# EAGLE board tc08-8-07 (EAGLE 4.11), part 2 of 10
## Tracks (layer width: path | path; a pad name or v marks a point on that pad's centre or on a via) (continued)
BAC_04  (via drill 0.61) (continued)
  Top 0.254: v315.63,163.5 316.58,162.55 v316.58,161.28 | v338.81,163.5 339.44,162.86 339.44,158.1 v339.13,157.79 | v344.52,153.98 345.16,153.34 v345.16,147.62 | v363.89,147.31 361.67,145.08 361.67,134.93 362.3,134.29 362.3,129.53 364.84,126.99 v364.84,119.05 | v357.86,115.88 355.95,115.88 355.95,103.49 356.27,103.18 356.27,99.36 355.32,98.41 355.32,86.35 v354.05,85.08 | v328.01,80.63 v328.01,74.6 | v281.98,74.92 282.29,75.24 282.29,94.28 280.71,95.87 v280.71,96.19 | v277.53,103.18 277.53,107.3 C07.N2
  Route15 0.254: v309.28,168.58 v306.74,171.12
  Bottom 0.254: C07.N2 278.17,108.57 280.39,110.8 C07.M2 | v306.74,171.12 306.42,171.12 304.84,172.71 302.3,172.71 300.71,174.3 B06.M1 | v309.28,168.58 312.46,165.4 314.04,165.4 314.68,164.77 314.68,163.5 v315.63,163.5 | v316.58,161.28 318.49,163.18 338.49,163.18 v338.81,163.5 | v339.13,157.79 340.71,156.2 340.71,155.24 342.94,155.24 344.21,153.98 v344.52,153.98 | v345.16,147.62 357.86,147.62 358.18,147.31 v363.89,147.31 | v364.84,119.05 364.84,115.88 v357.86,115.88 | v354.05,85.08 353.73,84.76 346.75,84.76 346.43,85.08 336.9,85.08 336.27,84.44 331.82,84.44 v328.01,80.63 | v328.01,74.6 310.23,74.6 309.92,74.92 v281.98,74.92 | v280.71,96.19 280.39,96.51 272.13,96.51 271.5,97.14 267.69,97.14 267.05,97.78 267.05,99.36 267.37,99.36 268.01,100 269.28,100 269.59,100.32 274.04,100.32 276.9,103.18 v277.53,103.18
BAC_04\  (via drill 0.61)
  Top 0.254: v271.5,52.38 274.36,52.38 v274.36,49.2 | v318.49,63.49 318.17,63.81 318.17,65.71 317.54,66.35 317.54,68.57 318.81,69.84 v318.81,70.16 | v330.55,81.9 330.55,90.16 329.92,90.79 329.92,95.87 327.7,98.1 327.7,100.63 327.38,100.95 327.38,116.19 v328.97,117.78 | v297.22,173.02 297.22,177.15 B06.L1 | v302.3,162.86 301.98,162.55 301.98,158.1 303.57,156.52 v303.57,155.24 | v306.42,152.39 306.74,152.07 306.74,150.17 306.42,149.85 306.42,146.04 v307.69,144.77
  Route2 0.254: v246.1,47.29 v254.67,55.87 | v268.64,52.06 271.18,52.06 v271.5,52.38 | v315.63,59.36 315.63,60.63 v318.49,63.49 | v297.22,173.02 298.8,171.44 296.9,169.53 296.9,168.26 v302.3,162.86 | v306.42,152.39 v303.57,155.24
  Route15 0.254: v259.12,54.28 259.12,53.33 v261.66,50.79 | v287.69,49.83 288.33,49.83 v294.68,43.49 | v318.81,70.16 323.25,74.6 324.52,74.6 326.74,76.82 v326.11,77.46 | v335.32,117.78 336.27,116.83 336.27,112.7 337.54,111.43 C03.M1 | v307.69,144.77 310.87,141.59 310.87,140.96 321.66,130.16 321.66,129.53 326.74,124.45 326.74,120.96 327.06,120.64 327.06,119.69 v328.97,117.78
  Bottom 0.254: v246.1,47.29 243.56,47.29 D10.K2 | v254.67,55.87 255.31,55.23 258.16,55.23 v259.12,54.28 | v261.66,50.79 262.93,52.06 v268.64,52.06 | v274.36,49.2 274.67,48.88 284.52,48.88 285.47,49.83 v287.69,49.83 | v294.68,43.49 294.99,43.17 298.8,43.17 315,59.36 v315.63,59.36 | v326.11,77.46 v330.55,81.9 | v328.97,117.78 329.92,118.73 334.36,118.73 v335.32,117.78
BAC_05
  Bottom 0.254: B07.R1 284.83,165.4 287.06,167.63 B07.P1 288.01,168.58 288.96,169.53 294.36,169.53 295.63,168.26 B06.P1
BAC_05\  (via drill 0.61)
  Top 0.254: v297.85,160.33 297.85,161.59 295.63,163.82 295.63,169.85 296.58,170.8 B06.N1 | v296.26,143.18 v296.26,148.89
  Route15 0.254: v297.85,160.33 297.85,159.69 298.49,159.05 298.49,157.47 298.8,157.15 298.8,152.07 295.95,149.21 v296.26,148.89 | v303.88,141.59 304.52,141.59 306.74,139.37 306.74,138.42 336.27,108.89 336.27,106.99 337.86,105.4 C03.P1
  Bottom 0.254: v296.26,143.18 297.22,142.23 298.8,142.23 299.44,141.59 v303.88,141.59
BAC_06  (via drill 0.61)
  Top 0.254: v278.8,71.74 278.48,72.06 278.48,86.35 279.75,87.62 279.75,133.34 282.93,136.51 282.93,141.91 283.25,142.23 283.25,149.53 281.34,151.43 281.34,154.93 B07.U2 280.39,155.88 278.17,158.1 B07.T2
  Bottom 0.254: v278.8,71.74 271.5,71.74 270.23,70.47 268.32,70.47 266.42,68.57 238.8,68.57 237.21,66.98 D11.C1 | B06.S1 299.44,161.59 299.12,161.28 296.9,161.28 295.95,160.33 279.75,160.33 278.48,159.05 B07.T2
BAC_06\  (via drill 0.61)
  Top 0.254: v335.95,98.73 336.27,99.05 336.27,103.18 v334.36,105.08 | v297.85,162.86 297.22,163.5 297.22,164.45 B06.R1
  Route15 0.254: v334.36,105.08 322.62,116.83 322.62,117.14 321.98,117.78 321.03,117.78 299.76,139.05 299.76,141.27 298.8,142.23 298.8,151.12 302.61,154.93 302.61,156.52 v299.76,159.37
  Bottom 0.254: v335.95,98.73 337.54,98.73 C03.S1 | v299.76,159.37 301.34,160.96 301.34,163.18 298.17,163.18 v297.85,162.86
BAC_07  (via drill 0.61)
  Top 0.254: v228.32,86.66 228.64,86.35 228.64,66.35 229.59,65.39 229.59,61.27 229.91,60.95 D11.E2 | 288.64,133.02 288.64,134.93 | v288.64,86.66 288.64,133.02 | 288.64,134.93 287.69,135.88 C07.C1 | 288.64,133.02 v287.06,133.02 | v288.33,152.39 288.64,152.07 288.64,134.93
  Bottom 0.254: v228.32,86.66 v288.64,86.66 | v287.06,133.02 284.83,133.02 C07.D1 | v288.33,152.39 289.6,153.66 294.68,153.66 295.95,154.93 299.12,154.93 299.44,155.24 B06.U1
BAC_07\  (via drill 0.61)
  Top 0.254: v325.16,101.27 324.2,102.22 324.2,107.62 v324.84,108.25 | v308.33,124.77 306.74,126.35 306.74,128.26 306.11,128.89 305.15,128.89 305.15,134.61 v305.47,134.93 | v297.22,141.27 297.22,151.75 B06.V1
  Route15 0.254: v325.16,101.27 v334.36,92.06 | v324.84,108.25 322.93,110.16 322.93,110.8 316.9,116.83 316.27,116.83 v308.33,124.77 | v305.47,134.93 305.15,134.93 v300.71,139.37
  Bottom 0.254: v300.71,139.37 298.8,141.27 v297.22,141.27 | v334.36,92.06 C03.U1
BAC_08  (via drill 0.61)
  Top 0.254: v231.49,125.08 231.49,97.78 231.18,97.46 231.18,93.65 231.49,93.33 231.49,91.43 230.54,90.47 230.54,81.27 232.13,79.68 232.13,52.38 233.08,51.42 D11.J1 233.08,50.15 233.08,47.29 228.95,43.17 228.95,34.6 228.32,33.96 228.32,27.61 228.64,27.29 228.64,2.53 v228.95,2.21 | v290.23,198.74 290.23,197.47 B06.D2 | v288.33,202.55 288.64,202.87 288.64,204.14 289.91,205.41 289.91,220.97 289.28,221.6 289.28,234.3 288.96,234.62 288.96,258.11 288.33,258.75 288.33,262.56 288.64,262.88 288.64,287.96 288.96,288.28 v288.96,290.5 | v26.71,286.69 7.66,267.64 7.66,251.45 7.97,251.13 7.97,180.33 7.34,179.69 7.34,179.06 7.97,178.42 7.97,76.82 7.34,76.19 7.34,75.55 8.61,74.28 8.61,3.48 v8.29,3.16
  Route2 0.254: v290.23,198.74 290.23,200.33 288.33,202.24 v288.33,202.55
  Bottom 0.254: v231.49,125.08 273.09,125.08 274.67,126.67 277.21,126.67 C07.F2 278.48,127.3 280.71,129.53 C07.E2 | v288.96,290.5 288.64,290.82 271.18,290.82 270.55,290.18 237.53,290.18 236.89,289.55 218.79,289.55 218.48,289.86 216.57,289.86 215.94,290.5 214.67,290.5 213.4,289.23 212.13,289.23 211.49,288.6 208.95,288.6 208.32,287.96 190.54,287.96 189.9,288.6 184.82,288.6 183.55,287.32 142.28,287.32 141.96,287.64 134.34,287.64 132.75,286.05 86.71,286.05 86.08,286.69 85.44,286.69 84.17,285.42 60.68,285.42 60.04,286.05 51.47,286.05 50.84,286.69 v26.71,286.69 | v8.29,3.16 9.56,3.16 10.83,1.89 228.64,1.89 v228.95,2.21
BAC_08\  (via drill 0.61)
  Top 0.254: v327.7,142.55 327.38,142.23 327.38,132.7 327.7,132.39 327.7,128.26 328.33,127.62 C03.F2 | v319.12,166.04 319.44,166.36 319.44,166.68 320.39,167.63 320.39,171.44 317.54,174.3 v317.54,174.93 | v299.76,195.25 299.76,199.38 B06.C1
  Route15 0.254: v327.7,142.55 327.7,151.43 327.38,151.75 327.38,157.79 v319.12,166.04 | v317.54,174.93 317.54,179.37 310.23,186.68 309.92,186.68 302.61,193.98 v302.61,194.3
  Bottom 0.254: v302.61,194.3 301.66,195.25 v299.76,195.25
BAC_09  (via drill 0.61)
  Top 0.254: v291.18,192.71 291.18,191.44 290.87,191.12 B06.F2 | v307.69,194.93 308.01,194.61 v308.01,191.44 | v318.17,196.52 321.03,199.38 v321.03,201.28 | v356.91,204.46 358.81,204.46 358.81,205.73 v359.13,206.05 | v360.72,182.55 359.76,181.6 359.76,179.06 358.81,178.11 358.81,168.26 358.49,167.95 358.49,149.53 357.54,148.58 v357.54,144.77 | v286.42,126.35 286.1,126.03 286.1,119.05 287.06,118.1 C07.K1
  Route2 0.254: v318.17,196.52 v313.09,191.44 | v315.63,134.93 313.09,134.93 v309.92,131.75 | v290.23,130.16 v286.42,126.35
  Bottom 0.254: C07.J1 284.52,120 286.74,117.78 C07.K1 | v291.18,192.71 291.5,192.39 300.71,192.39 301.66,193.34 304.2,193.34 305.79,194.93 v307.69,194.93 | v308.01,191.44 308.33,191.76 312.77,191.76 v313.09,191.44 | v321.03,201.28 329.6,201.28 332.78,204.46 v356.91,204.46 | v359.13,206.05 360.4,204.77 362.3,204.77 364.21,202.87 366.75,202.87 367.38,202.24 367.38,182.55 v360.72,182.55 | v357.54,144.77 364.84,137.46 364.84,134.61 352.46,134.61 351.83,133.97 348.97,133.97 348.02,134.93 340.08,134.93 339.13,133.97 336.27,133.97 335.63,134.61 327.06,134.61 326.43,133.97 323.57,133.97 322.62,134.93 v315.63,134.93 | v309.92,131.75 309.6,132.07 292.45,132.07 290.55,130.16 v290.23,130.16
BAC_09\  (via drill 0.61)
  Top 0.254: v294.04,179.37 294.99,180.33 294.99,192.08 294.04,193.03 B06.E2 | v296.58,179.37 298.17,179.37 298.17,169.53 v297.85,169.21 | v328.01,124.13 328.33,123.81 328.33,121.27 C03.J2
  Route2 0.254: v296.58,179.37 v294.04,179.37 | v297.85,169.21 298.8,168.26 298.8,167.63 302.61,163.82 302.93,163.82 304.84,161.91 303.57,160.64 v303.57,160.33
  Route15 0.254: v303.57,160.33 311.19,152.71 311.19,150.8 312.46,149.53 312.46,146.67 319.44,139.69 319.44,138.1 326.74,130.8 326.74,125.4 v328.01,124.13
BAC_10\  (via drill 0.61)
  Top 0.254: v353.41,131.11 354.37,130.16 355.95,130.16 355.95,135.88 355.64,136.2 355.64,136.83 357.86,139.05 357.86,140.64 v360.72,143.5 | v364.21,157.15 363.57,157.79 v363.57,160.33 | v347.7,192.08 347.06,192.71 v347.06,193.98 | v348.97,210.81 348.97,212.39 349.6,213.03 349.6,222.24 348.97,222.87 v348.97,224.14 | v369.61,227 369.92,227.32 369.92,243.83 v368.02,245.73 | v366.11,247.32 366.43,247.64 v366.43,274.31 | v253.08,285.1 250.54,282.56 v250.54,267 | v294.04,189.85 294.04,187.95 B06.H2 | v328.01,212.71 v328.01,205.73
  Route2 0.254: v341.03,128.58 340.08,127.62 340.08,126.99 338.17,125.08 337.54,125.08 328.97,116.51 328.97,114.92 C03.L2 | v348.02,129.53 348.33,129.53 350.24,131.43 350.87,131.43 351.83,132.39 352.46,132.39 353.41,131.43 v353.41,131.11 | v344.52,198.11 342.3,200.33 343.57,201.6 343.57,203.51 346.11,206.05 346.11,207.95 v348.97,210.81 | v300.71,189.85 302.93,192.08 307.38,192.08 307.69,192.39 308.33,192.39 v318.17,202.24 | v328.01,205.73 v325.79,203.51
  Route15 0.254: v363.89,144.77 363.89,146.04 362.94,146.99 v362.94,151.12
  Bottom 0.254: v341.03,128.58 341.35,128.89 347.38,128.89 v348.02,129.53 | v360.72,143.5 361.99,144.77 v363.89,144.77 | v362.94,151.12 364.84,153.02 364.84,157.15 v364.21,157.15 | v363.57,160.33 363.26,160.64 362.94,160.64 361.67,161.91 361.67,163.82 355.95,163.82 355.64,164.14 355,164.14 354.68,163.82 347.06,163.82 346.43,164.45 346.43,166.36 348.33,166.36 348.97,166.99 357.86,166.99 358.49,167.63 358.49,170.49 357.86,170.49 348.97,179.37 348.97,192.08 v347.7,192.08 | v347.06,193.98 344.52,196.52 v344.52,198.11 | v348.97,224.14 348.97,226.68 352.46,226.68 353.1,226.05 355.95,226.05 356.91,227 v369.61,227 | v368.02,245.73 366.43,247.32 v366.11,247.32 | v366.43,274.31 366.43,283.83 355,283.83 353.73,285.1 v253.08,285.1 | v250.54,267 250.23,267.32 247.37,267.32 246.73,267.96 244.19,267.96 242.92,266.69 A10.D2 | v294.04,189.85 294.68,189.22 300.07,189.22 v300.71,189.85 | v318.17,202.24 321.35,202.24 321.66,201.92 324.2,201.92 v325.79,203.51 | v328.01,212.71 328.33,212.39 349.29,212.39 349.6,212.71 350.24,212.71 350.87,212.08 350.87,210.81 v348.97,210.81
BAC_11\  (via drill 0.61)
  Top 0.254: v232.45,96.83 231.81,96.19 231.81,93.97 232.13,93.65 232.13,88.25 232.45,87.94 v232.45,81.58 | v253.08,74.6 254.35,74.6 255.94,76.19 259.12,76.19 259.12,76.5 v259.43,76.82 | v267.69,75.87 272.77,75.87 273.72,76.82 v274.67,76.82 | v254.99,153.98 256.26,152.71 v256.26,144.77 | v254.67,126.67 253.72,125.72 253.72,118.73 v252.13,117.14
  Route2 0.254: 233.4,99.68 234.35,98.73 v232.45,96.83 | 233.4,99.68 230.86,102.22 230.22,102.22 229.91,101.91 227.68,101.91 C11.R2 | v247.05,80.63 v253.08,74.6 | v299.12,82.22 299.12,82.86 304.52,88.25 304.52,92.06 319.76,107.3 v320.08,107.3 | v258.48,174.3 255.31,171.12 255.31,169.85 254.35,168.9 254.35,166.04 v254.99,165.4 | v252.13,117.14 239.75,104.76 238.48,104.76 233.4,99.68
  Route15 0.254: v286.42,178.11 285.79,178.11 284.83,179.06 283.25,179.06 v282.61,178.42 | v244.51,161.59 244.51,158.42 v246.1,156.83 | v256.26,144.77 256.26,144.13 260.07,140.32 260.07,130.16 v261.66,128.58
  Bottom 0.254: v232.45,81.58 233.08,80.95 246.73,80.95 v247.05,80.63 | v259.43,76.82 259.75,77.14 266.42,77.14 v267.69,75.87 | v274.67,76.82 279.75,76.82 280.71,77.77 294.68,77.77 v299.12,82.22 | v320.08,107.3 320.71,106.67 327.06,106.67 328.01,107.62 C03.N2 | v286.42,178.11 286.74,178.11 287.69,179.06 291.5,179.06 293.09,180.64 B06.K2 | v282.61,178.42 281.98,179.06 275.31,179.06 272.13,175.88 260.07,175.88 v258.48,174.3 | v254.99,165.4 253.4,163.82 249.91,163.82 249.27,164.45 247.37,164.45 v244.51,161.59 | v246.1,156.83 250.86,156.83 253.72,153.98 v254.99,153.98 | v261.66,128.58 259.75,130.48 258.48,130.48 v254.67,126.67
BLK_IN_SYNC  (via drill 0.61)
  Top 0.254: v200.06,83.49 v200.06,95.87 | v146.4,85.39 146.4,100.63 145.77,101.27 v145.77,104.44 | v217.21,131.75 216.25,130.8 216.25,123.18 216.89,122.54 216.89,119.69 215.3,118.1 v215.3,116.51 | v221.97,116.19 221.97,113.65 v219.75,111.43 | v209.59,107.94 209.9,107.62 209.9,103.18 211.17,101.91 C13.S1
  Bottom 0.254: v200.06,95.87 200.7,96.51 204.82,96.51 206.73,98.41 C13.S1 | v200.06,83.49 199.74,83.81 194.03,83.81 192.76,85.08 185.77,85.08 185.14,84.44 182.28,84.44 181.01,85.71 146.72,85.71 v146.4,85.39 | v145.77,104.44 141.96,104.44 CD18.AP2 | v217.21,131.75 228.32,131.75 229.59,130.48 C11.E2 | v215.3,116.51 215.62,116.19 v221.97,116.19 | v219.75,111.43 218.16,109.84 212.76,109.84 210.86,107.94 v209.59,107.94
BLK_IN_SYNC\  (via drill 0.61)
  Top 0.254: v238.8,54.28 238.8,52.06 239.43,51.42 D10.J2 | v203.55,52.69 200.38,55.87 200.38,77.46 200.7,77.77 200.7,78.73 199.11,80.32 v199.11,89.21 | v247.69,270.18 248.64,271.13 248.64,275.26 248.96,275.58 A10.A1 | v203.24,260.66 v203.24,262.56 | v197.52,259.38 193.71,255.58 v193.71,253.67 | v183.23,243.83 183.87,243.19 183.87,239.38 182.92,238.43 182.92,236.52 183.87,235.57 183.87,232.71 v181.96,230.81 | v180.06,230.18 180.38,229.86 180.38,226.36 180.69,226.05 180.69,218.11 181.33,217.48 v181.33,213.03 | v172.76,203.51 171.8,202.55 171.8,198.74 v173.39,197.15 | v170.85,193.34 171.17,193.03 171.17,189.54 170.22,188.58 v170.22,188.27 | v178.79,159.69 178.15,159.05 178.15,154.61 178.47,154.29 178.47,153.34 177.52,152.39 177.52,151.12 175.93,149.53 175.93,143.5 v176.25,143.18
  Route2 0.254: v199.11,89.21 205.14,95.24 205.14,96.83 206.09,97.78 206.09,99.36 207.68,100.95 C13.R1 | v247.69,270.18 245.78,270.18 236.57,260.97 234.67,260.97 233.4,262.24 v230.54,259.38 | v193.71,253.67 193.08,253.67 v183.23,243.83 | v181.33,213.03 178.79,210.49 178.47,210.49 174.98,207 174.98,205.73 v172.76,203.51 | v173.39,197.15 173.39,195.89 v170.85,193.34 | v170.22,188.27 172.76,185.73 171.49,184.46 171.49,181.6 171.8,181.28 171.8,175.56 170.22,173.98 170.22,173.02 171.49,171.76 171.49,171.12 170.53,170.17 170.53,168.58 179.11,160.01 v178.79,159.69
  Route15 0.254: v218.48,261.29 217.21,261.29 v214.67,263.83 | v176.25,143.18 176.57,143.18 181.96,137.78 181.96,137.46 182.6,136.83 183.23,136.83 205.78,114.29 205.78,112.07 206.09,111.75 206.09,103.81 207.68,102.22 C13.R1
  Bottom 0.254: v238.8,54.28 237.21,52.69 v203.55,52.69 | v230.54,259.38 230.22,259.07 224.83,259.07 222.29,261.61 218.79,261.61 v218.48,261.29 | v214.67,263.83 213.08,262.24 209.9,262.24 209.59,262.56 205.78,262.56 205.46,262.24 203.55,262.24 v203.24,262.56 | v203.24,260.66 203.24,259.07 197.84,259.07 v197.52,259.38 | v181.96,230.81 181.33,230.18 v180.06,230.18
BMB_00
  Bottom 0.254: C08.B1 272.13,140.01 273.09,140.96 292.77,140.96 293.72,140.01 296.26,140.01 C06.B1
BMB_00\  (via drill 0.61)
  Top 0.254: v300.71,148.58 300.71,143.81 300.39,143.5 C06.A1 | v347.06,149.21 346.75,148.89 346.75,140.96 347.38,140.32 C02.B1
  Bottom 0.254: v300.71,148.58 301.03,148.26 313.09,148.26 313.73,148.89 320.39,148.89 320.71,149.21 v347.06,149.21
BMB_01
  Bottom 0.254: C08.H1 275.31,124.13 276.26,125.08 279.12,125.08 282.61,128.58 295.95,128.58 297.22,129.84 299.44,129.84 C06.E1
BMB_01\  (via drill 0.61)
  Top 0.254: v297.22,136.83 297.22,133.97 C06.D1 | v305.47,138.74 306.42,139.69 306.42,140.96 308.65,143.18 308.65,150.17 v308.33,150.48 | v355.32,151.12 355.32,137.46 355,137.15 355,134.29 355.32,133.97 355.32,131.75 v354.68,131.11
  Bottom 0.254: v297.22,136.83 298.17,137.78 304.52,137.78 v305.47,138.74 | v308.33,150.48 308.65,150.17 319.76,150.17 320.39,150.8 355,150.8 v355.32,151.12 | v354.68,131.11 353.73,130.16 C02.E1
BMB_02
  Bottom 0.254: C08.N1 272.13,108.25 273.09,109.21 276.26,109.21 283.25,116.19 288.96,116.19 296.26,123.49 299.44,123.49 C06.H1
BMB_02\  (via drill 0.61)
  Top 0.254: v305.47,127.94 305.15,127.62 305.15,109.21 307.69,106.67 v307.69,103.49 | v355.32,102.86 v355.32,123.49
  Bottom 0.254: v305.47,127.94 305.15,128.26 298.49,128.26 297.53,127.3 C06.F1 | v307.69,103.49 310.55,103.49 311.19,102.86 v355.32,102.86 | v355.32,123.49 351.51,123.49 C02.H1
BMB_03  (via drill 0.61)
  Top 0.254: v269.91,123.81 269.91,124.13 268.96,125.08 268.96,129.21 268.64,129.53 C08.E2 | v293.41,121.91 v293.41,119.05
  Bottom 0.254: v269.91,123.81 270.55,123.18 273.4,123.18 274.04,122.54 279.44,122.54 280.07,121.91 v293.41,121.91 | v293.41,119.05 293.72,118.73 297.22,118.73 298.17,117.78 299.44,117.78 C06.K1
BMB_03\  (via drill 0.61)
  Top 0.254: v307.38,119.69 308.01,119.05 308.01,107.94 308.33,107.62 308.33,104.76 311.19,101.91 v311.19,100.95 | v339.13,100.95 339.44,101.27 339.44,112.38 v339.13,112.7 | v350.56,112.7 350.56,116.83 C02.K1
  Bottom 0.254: v307.38,119.69 307.06,119.37 298.49,119.37 297.53,120.32 C06.J1 | v311.19,100.95 311.82,100.32 338.49,100.32 v339.13,100.95 | v339.13,112.7 v350.56,112.7
BMB_04  (via drill 0.61)
  Top 0.254: v265.15,109.52 C08.L2
  Bottom 0.254: v265.15,109.52 265.47,109.21 268.32,109.21 270.86,106.67 280.71,106.67 283.25,109.21 294.04,109.21 295.95,111.11 C06.M1
BMB_04\  (via drill 0.61)
  Top 0.254: v300.39,106.67 v300.39,109.52 | v306.11,102.86 308.01,100.95 v308.01,97.78 | v320.71,97.14 320.39,97.46 320.39,103.81 v320.71,104.13 | v350.56,106.35 350.56,110.48 C02.M1
  Bottom 0.254: v300.39,109.52 301.03,110.16 301.34,110.16 301.34,111.75 300.71,112.38 299.12,112.38 297.53,113.97 C06.L1 | v300.39,106.67 301.98,105.08 303.88,105.08 v306.11,102.86 | v308.01,97.78 308.33,97.46 311.82,97.46 312.14,97.14 v320.71,97.14 | v320.71,104.13 321.35,103.49 346.43,103.49 349.29,106.35 v350.56,106.35
BMB_05
  Bottom 0.254: C08.S2 268.96,98.73 269.91,99.68 292.14,99.68 292.77,100.32 297.53,100.32 299.76,102.54 299.76,104.13 C06.P1
BMB_05\  (via drill 0.61)
  Top 0.254: v284.52,106.03 282.93,104.44 282.93,99.68 v283.88,98.73 | v308.96,99.68 310.87,97.78 v310.87,96.51 | v350.24,100.32 350.56,100.63 350.56,104.13 C02.P1
  Bottom 0.254: v284.52,106.03 291.82,106.03 292.45,106.67 295.31,106.67 296.26,107.62 C06.N1 | v283.88,98.73 285.47,97.14 288.96,97.14 290.87,99.05 292.45,99.05 293.09,99.68 v308.96,99.68 | v310.87,96.51 320.08,96.51 320.39,96.19 321.35,96.19 321.98,96.83 329.92,96.83 330.24,96.51 334.36,96.51 334.68,96.83 336.9,96.83 337.22,96.51 346.43,96.51 v350.24,100.32
BMB_06  (via drill 0.61)
  Top 0.254: v295.95,98.41 295.63,98.73 295.63,104.76 v295.95,105.08 | v293.41,126.99 292.77,127.62 292.77,129.21 292.45,129.53 292.45,133.34 v293.72,134.61 | v294.68,138.1 294.36,138.42 v294.36,140.96 | v290.55,143.5 290.23,143.81 v290.23,148.89
  Route2 0.254: v293.72,134.61 295.31,136.2 295.31,137.46 v294.68,138.1
  Route15 0.254: v295.95,105.08 295.95,106.99 295.63,107.3 295.63,109.52 295.31,109.84 295.31,117.14 298.8,120.64 298.49,120.96 298.49,121.91 v293.41,126.99 | v293.41,148.89 295.95,151.43 295.63,151.75 295.63,158.1 295.31,158.42 295.31,162.86 284.2,173.98 284.2,175.56 279.75,180.01 279.75,185.09 274.04,190.8 274.04,192.39 273.4,193.03 273.4,200.96 271.82,202.55 B08.B1
  Bottom 0.254: v294.36,140.96 294.04,141.27 293.41,141.27 291.18,143.5 v290.55,143.5 | v290.23,148.89 v293.41,148.89 | v295.95,98.41 C06.S1
BMB_06\  (via drill 0.61)
  Top 0.254: v275.63,100.63 275.94,100.32 275.94,88.89 274.99,87.94 v274.99,84.76 | v351.19,93.65 351.19,97.78 C02.S1
  Bottom 0.254: v275.63,100.63 275.94,100.32 291.18,100.32 291.82,100.95 295.95,100.95 296.26,101.27 C06.R1 | v274.99,84.76 282.29,84.76 283.56,86.03 288.01,86.03 288.33,85.71 335.63,85.71 336.27,86.35 350.24,86.35 350.56,86.03 351.19,86.03 352.14,86.98 352.14,93.65 v351.19,93.65
BMB_07  (via drill 0.61)
  Top 0.254: v299.76,95.55 299.76,92.7 C06.U1 | v269.91,130.16 270.23,130.48 270.23,141.91 270.55,142.23 270.55,151.43 269.59,152.39 269.59,156.83 269.28,157.15 269.28,160.96 269.59,161.28 v269.59,172.39 | v274.99,191.12 274.99,193.03 B08.E1
  Route2 0.254: v269.59,172.39 269.59,172.71 270.86,173.98 270.86,176.2 268.64,178.42 270.23,180.01 270.23,186.36 v274.99,191.12
  Route15 0.254: v299.76,95.55 299.76,95.87 291.82,103.81 291.82,108.57 290.23,110.16 290.23,111.11 289.28,112.07 289.28,113.33 278.17,124.45 277.53,124.45 273.4,128.58 273.4,128.89 272.77,129.53 270.55,129.53 v269.91,130.16
BMB_07\
  Bottom 0.254: C06.V1 297.53,88.57 299.76,86.35 330.55,86.35 334.36,90.16 348.65,90.16 350.24,91.74 C02.U1
BMB_08  (via drill 0.61)
  Top 0.254: v290.23,136.2 290.23,133.97 C06.D2 | v280.71,139.37 282.29,140.96 282.29,142.23 282.61,142.55 282.61,147.62 279.44,150.8 279.44,155.56 v279.12,155.88 | v279.44,164.77 280.39,163.82 281.66,163.82 281.66,166.99 282.93,168.26 282.93,173.66 283.56,174.3 283.56,176.2 279.75,180.01 279.75,184.77 v280.71,185.73
  Route15 0.254: v279.12,155.88 279.12,164.45 v279.44,164.77
  Bottom 0.254: v290.23,136.2 288.01,138.42 288.01,139.37 285.79,139.37 284.83,138.42 283.56,138.42 282.93,139.05 282.93,140.32 281.66,140.32 v280.71,139.37 | v280.71,185.73 279.12,187.31 279.12,188.9 275.94,188.9 271.5,193.34 268.96,193.34 B08.E2
BMB_08\  (via drill 0.61)
  Top 0.254: v339.44,140.96 339.44,127.62 v339.13,127.3
  Bottom 0.254: v339.44,140.96 334.36,140.96 334.05,140.64 330.24,140.64 329.92,140.96 321.66,140.96 320.71,140.01 318.17,140.01 316.58,138.42 306.42,138.42 305.15,137.15 301.03,137.15 300.71,136.83 C06.C1 | v339.13,127.3 340.71,127.3 C02.F2
BMB_09  (via drill 0.61)
  Top 0.254: v307.69,126.67 307.69,135.88 308.33,136.51 308.33,140.32 309.28,141.27 v309.92,141.27 | v311.82,141.27 311.5,141.59 v311.5,149.21 | v370.56,166.99 v370.56,157.47 | v323.89,209.22 323.57,208.9 323.57,193.66 v323.25,193.34 | v279.44,189.85 279.12,189.54 v279.12,174.93
  Bottom 0.254: v307.69,126.67 307.38,126.35 304.84,126.35 304.2,125.72 292.14,125.72 291.18,126.67 C06.F2 | v311.82,141.27 v309.92,141.27 | v311.5,149.21 311.82,149.53 320.08,149.53 320.71,150.17 363.26,150.17 v370.56,157.47 | v370.56,166.99 370.56,209.22 v323.89,209.22 | v323.25,193.34 322.3,192.39 301.66,192.39 301.03,191.76 282.93,191.76 281.02,189.85 v279.44,189.85 | v279.12,174.93 275.31,174.93 B08.M1
BMB_09\  (via drill 0.61)
  Top 0.254: v320.71,129.53 321.03,129.21 321.03,120 v321.98,119.05
  Bottom 0.254: v320.71,129.53 320.08,128.89 305.79,128.89 303.25,131.43 295.31,131.43 294.36,130.48 C06.E2 | v321.98,119.05 322.3,119.37 337.22,119.37 337.54,119.69 340.08,119.69 340.71,120.32 C02.J2
BMB_10  (via drill 0.61)
  Top 0.254: v290.23,125.08 290.23,121.27 C06.J2 | v280.71,127.94 v280.71,125.4 | v274.99,128.26 v274.99,125.72 | v272.45,128.58 272.77,128.89 272.77,142.55 272.13,143.18 272.13,151.12 272.77,151.75 272.77,156.52 v272.45,156.83 | v274.36,157.15 v274.36,159.69 | v272.45,160.96 271.82,161.59 271.82,164.45 B08.R1
  Bottom 0.254: v290.23,125.08 289.91,125.4 v280.71,125.4 | v280.71,127.94 278.48,125.72 v274.99,125.72 | v274.99,128.26 274.67,128.58 v272.45,128.58 | v272.45,156.83 272.77,157.15 v274.36,157.15 | v274.36,159.69 273.09,160.96 v272.45,160.96
BMB_10\  (via drill 0.61)
  Top 0.254: v294.36,120 294.36,122.86 294.04,123.18 C06.H2 | v334.36,109.52 335,110.16 v335,112.07
  Bottom 0.254: v294.36,120 294.99,119.37 297.53,119.37 298.17,118.73 308.33,118.73 308.65,119.05 313.09,119.05 314.04,118.1 314.04,115.56 308.65,115.56 305.15,112.07 305.15,109.84 323.25,109.84 323.89,109.21 334.05,109.21 v334.36,109.52 | v335,112.07 336.9,113.97 340.71,113.97 C02.L2
BMB_11  (via drill 0.61)
  Top 0.254: v290.23,118.73 290.23,114.92 C06.L2 | v276.9,130.48 276.58,130.8 276.58,136.2 v276.26,136.51 | v269.28,139.37 269.59,139.69 269.59,142.23 269.91,142.55 269.91,149.85 v269.28,150.48 | v266.1,162.86 266.42,163.18 266.42,166.04 264.83,167.63 v264.83,168.26 | v274.99,176.2 274.36,176.83 v274.36,179.37
  Route2 0.254: v271.18,137.46 v269.28,139.37 | v259.75,156.52 v266.1,162.86 | v274.36,172.39 275.94,173.98 275.94,175.25 v274.99,176.2
  Route15 0.254: v287.37,120 v276.9,130.48 | v274.36,179.37 273.4,180.33 273.4,181.92 271.82,183.5 B08.J1
  Bottom 0.254: v290.23,118.73 288.96,120 v287.37,120 | v276.26,136.51 276.26,137.78 271.5,137.78 v271.18,137.46 | v269.28,150.48 262.93,150.48 260.07,153.34 260.07,156.52 v259.75,156.52 | v264.83,168.26 264.83,170.17 266.42,170.17 266.74,170.49 270.55,170.49 270.86,170.17 272.13,170.17 v274.36,172.39
BMB_11\  (via drill 0.61)
  Top 0.254: v308.96,118.1 311.19,115.88 v311.19,108.25
  Bottom 0.254: v308.96,118.1 307.06,116.19 295.31,116.19 294.36,117.14 C06.K2 | v311.19,108.25 313.41,106.03 336.27,106.03 338.17,107.94 C02.N2
BMB_TO_DTB  (via drill 0.61)
  Top 0.254: 271.18,124.77 271.18,126.35 C08.F1 | 271.18,124.77 271.18,123.81 269.28,121.91 269.28,118.73 268.64,118.1 C08.K2 | 273.4,122.54 273.4,116.83 274.36,115.88 274.36,111.75 C08.M1 | 271.18,124.77 273.4,122.54 | 273.4,122.54 273.4,141.27 274.36,142.23 C08.A1 274.36,143.5 274.36,153.98 273.4,154.93 273.4,171.44 | B08.A1 274.04,206.05 274.04,201.28 273.4,200.65 273.4,188.9 274.36,187.95 B08.H1 274.36,186.68 273.4,185.73 273.4,173.98 273.72,173.66 273.72,173.02 272.77,172.07 | 273.4,171.44 274.36,170.49 274.36,168.9 B08.P1 | 273.4,171.44 272.77,172.07 | 272.77,172.07 271.82,173.02 271.82,177.15 B08.L1 271.18,178.42 270.23,179.37 270.23,195.25 271.18,196.2 B08.D1 | v221.97,75.87 221.97,46.03 221.02,45.07 D12.L1 | v263.24,76.19 263.24,96.83 264.83,98.41 264.83,100.95 C08.R2 264.83,102.22 263.88,103.18 263.88,127.62 265.15,128.89 265.15,130.48 | 265.15,130.48 C08.D2 | 265.15,130.48 v265.47,130.48
  Bottom 0.254: B08.D1 B08.D2 | v221.97,75.87 262.93,75.87 v263.24,76.19 | v265.47,130.48 267.05,128.89 269.28,128.89 270.86,127.3 C08.F1
BMR00  (via drill 0.61)
  Top 0.254: v85.44,260.02 86.08,259.38 86.08,240.65 87.67,239.06 v87.67,238.43 | v96.56,236.21 97.19,235.57 v97.19,234.3 | v121.32,233.35 121,233.03 121,229.22 121.64,228.59 121.64,226.68 120.69,225.73 v120.69,221.92 | v150.21,210.81 151.17,209.86 v151.17,207
  Route15 0.254: v120.69,221.92 120.69,220.02 v122.59,218.11 | v151.17,207 151.48,207 156.56,201.92 160.37,201.92 190.22,172.07 190.22,170.49 191.81,168.9 B14.P2
  Bottom 0.254: v85.44,260.02 81.63,260.02 A23.F1 | v87.67,238.43 89.25,236.84 95.92,236.84 v96.56,236.21 | v97.19,234.3 98.14,233.35 v121.32,233.35 | v122.59,218.11 124.81,215.89 145.45,215.89 150.21,211.12 v150.21,210.81
BMR00\  (via drill 0.61)
  Top 0.254: v84.49,254.94 84.49,256.53 A23.H1 | v128.31,255.58 129.26,254.62 129.26,252.08 130.21,251.13 130.21,241.61 127.35,238.75 127.35,232.4 127.04,232.08 127.04,229.54 v127.35,229.22 | v131.48,225.09 130.53,224.14 130.53,211.44 130.85,211.12 130.85,204.14 130.53,203.82 130.53,196.2 130.85,195.89 130.85,191.44 130.53,191.12 130.53,189.85 132.12,188.27 v132.12,187.63
  Route2 0.254: v131.48,225.09 v127.35,229.22
  Route15 0.254: v161.96,186.68 162.91,186.68 168.63,180.96 170.53,180.96 v186.09,165.4
  Bottom 0.254: v84.49,254.94 84.81,255.26 124.81,255.26 125.13,255.58 v128.31,255.58 | v132.12,187.63 133.7,186.04 161.01,186.04 161.64,186.68 v161.96,186.68 | v186.09,165.4 188.31,165.4 B14.R2
BMR01  (via drill 0.61)
  Top 0.254: v82.59,268.59 82.59,271.13 81.32,272.4 A23.B1 | v104.49,266.37 105.13,265.74 105.13,246.37 v106.72,244.78 | v152.12,242.56 152.75,241.92 v152.75,228.9 | v160.37,222.24 160.69,221.92 v160.69,213.03 | v164.82,212.39 v169.58,207.63
  Route2 0.254: v157.52,225.09 v160.37,222.24
  Route15 0.254: v169.58,207.63 176.25,207.63 180.38,203.51 180.69,203.51 181.33,202.87 181.33,202.24 191.49,192.08 191.49,191.76 192.12,191.12 194.35,191.12 194.66,190.8 B14.F1
  Bottom 0.254: v82.59,268.59 83.22,267.96 95.29,267.96 95.92,267.32 98.78,267.32 99.41,267.96 101.32,267.96 102.91,266.37 v104.49,266.37 | v106.72,244.78 108.94,242.56 v152.12,242.56 | v152.75,228.9 156.56,225.09 v157.52,225.09 | v160.69,213.03 161.33,212.39 v164.82,212.39
BMR01\  (via drill 0.61)
  Top 0.254: v91.48,254.3 88.62,257.16 88.62,263.51 86.08,266.05 86.08,269.86 85.13,270.81 85.13,274.94 84.49,275.58 A23.A1 | v134.66,252.4 v136.56,254.3 | v162.28,257.16 v165.14,260.02 | v169.58,262.88 171.8,260.66 171.8,254.3 172.44,253.67 172.44,252.08 171.8,251.45 171.8,242.24 v173.39,240.65 | v185.46,229.86 185.46,227 184.5,226.05 v184.5,222.55 | v187.04,222.55 186.09,221.6 v186.09,216.21 | v188.63,215.57 189.58,214.62 v189.58,207.63
  Route15 0.254: v173.39,240.65 v181.96,232.08 | v189.58,207.63 189.58,204.46 196.57,197.47 196.57,195.89 198.16,194.3 B14.E1
  Bottom 0.254: v91.48,254.3 96.24,249.54 110.84,249.54 113.38,252.08 124.5,252.08 124.81,251.77 127.67,251.77 128.31,252.4 v134.66,252.4 | v136.56,254.3 137.51,255.26 160.37,255.26 v162.28,257.16 | v165.14,260.02 167.99,262.88 v169.58,262.88 | v181.96,232.08 184.19,229.86 v185.46,229.86 | v184.5,222.55 v187.04,222.55 | v186.09,216.21 186.73,215.57 v188.63,215.57
C00  (via drill 0.61)
  Top 0.254: v181.33,148.58 181.33,136.51 180.69,135.88 180.69,131.75 179.74,130.8 C15.E2 | v41.63,274.31 41.63,265.74 40.04,264.15 A26.E2 | v212.76,280.66 212.44,280.34 212.44,250.18 214.03,248.59 214.03,248.27 A12.L2 214.03,247 213.08,246.05 213.08,220.33 214.35,219.06 214.35,205.09 213.08,203.82 213.08,168.26 214.03,167.31 214.03,165.72 B12.R2 214.03,164.45 211.81,162.23 B13.S1 211.49,161.28 212.44,160.33 212.44,149.53 v211.81,148.89 212.76,147.94 212.76,146.99 212.44,146.67 v212.44,86.03 | v250.23,84.76 250.23,79.68 250.54,79.36 250.54,68.25 249.59,67.3 D10.C1
  Bottom 0.254: v181.33,148.58 181.65,148.26 188.63,148.26 188.95,148.58 205.14,148.58 205.46,148.89 v211.81,148.89 | v41.63,274.31 42.26,274.94 53.06,274.94 57.19,279.07 136.24,279.07 137.83,280.66 138.47,280.66 138.78,280.34 212.44,280.34 v212.76,280.66 | v250.23,84.76 241.65,84.76 241.02,85.39 229.27,85.39 228.95,85.08 226.1,85.08 224.83,86.35 212.76,86.35 v212.44,86.03
C00\  (via drill 0.61)
  Top 0.254: v180.06,148.58 177.52,146.04 177.52,122.22 176.57,121.27 C15.J2 | v187.04,164.45 187.04,185.73 186.09,186.68 B15.H1 186.09,187.95 186.09,192.08 187.68,193.66 187.68,217.16 v188.63,218.11 | v195.62,237.16 193.39,234.94 193.39,223.83 192.76,223.19 v192.76,218.11 | B13.U1 210.86,156.2 210.22,156.83 210.22,160.96 209.9,161.28 209.9,166.68 210.86,167.63 B13.P1
  Bottom 0.254: v180.06,148.58 181.01,149.53 184.82,149.53 185.46,148.89 188.31,148.89 188.63,149.21 204.82,149.21 206.09,150.48 208.95,150.48 210.86,152.39 210.86,154.93 B13.U1 | B13.P1 210.86,167.63 210.86,166.04 208.63,163.82 207.05,163.82 205.46,162.23 B13.S2 201.01,161.91 199.74,163.18 188.31,163.18 v187.04,164.45 | v195.62,237.16 195.93,236.84 215.94,236.84 216.89,237.8 A12.P2 | v188.63,218.11 v192.76,218.11
C01  (via drill 0.61)
  Top 0.254: 228.32,170.8 228.32,180.01 228.95,180.64 228.95,181.6 v229.91,182.55 | 228.32,170.8 228.32,158.1 227.37,157.15 227.37,153.02 B11.V2 | v206.41,170.49 206.41,170.17 205.14,168.9 B13.P2 | 228.32,170.8 v228.64,170.8 | v37.82,278.43 37.82,268.91 38.14,268.59 38.14,266.37 37.82,266.05 37.82,261.93 36.87,260.97 A26.F2 | v213.71,285.74 213.71,274.31 213.08,273.67 213.08,252.72 218.16,247.64 218.16,244.78 A12.M2 217.52,240.97 218.79,239.7 218.79,227.95 221.33,225.41 221.33,223.51 v222.29,222.55 | v247.69,193.03 244.83,195.89 244.83,220.65 244.19,221.29 v244.19,223.51
  Bottom 0.254: v229.91,182.55 230.22,182.87 244.51,182.87 245.46,183.82 B10.J1 246.42,184.77 246.42,189.22 246.73,189.22 247.69,190.17 v247.69,193.03 | v206.41,170.49 206.73,170.17 228,170.17 v228.64,170.8 | v37.82,278.43 43.53,284.15 57.5,284.15 58.77,282.88 134.34,282.88 135.93,284.47 140.37,284.47 140.69,284.15 185.14,284.15 186.41,285.42 188.31,285.42 188.95,284.79 209.9,284.79 210.54,285.42 213.4,285.42 v213.71,285.74 | v244.19,223.51 226.1,223.51 225.14,222.55 v222.29,222.55
C01\  (via drill 0.61)
  Top 0.254: B13.R2 202.28,165.4 202.92,166.04 202.92,169.53 204.82,171.44 B13.M2 204.51,175.25 203.55,176.2 203.55,182.87 v204.19,183.5 | v216.57,234.62 216.25,234.3 216.25,219.06 214.98,217.79 214.98,204.46 215.94,203.51 215.94,199.38 216.25,199.06 216.25,198.43 | 216.25,198.43 216.25,186.36 v216.89,185.73 | D10.D1 245.78,64.12 245.46,64.44 245.46,68.57 244.83,69.2 244.83,94.6 244.51,94.92 244.51,96.19 244.83,96.51 244.83,125.72 v244.51,126.03 v244.51,129.21 | v248.96,163.5 248.96,167.63 B10.P1 248.96,168.9 v248.96,171.76 | v248.96,160.33 248.64,160.01 248.64,156.83 248,156.2 248,146.04 251.18,142.86 251.18,130.8 v251.5,130.48 | v216.57,198.43 216.25,198.43 | v242.29,190.17 241.65,189.54 241.65,177.47 v242.61,176.52
  Bottom 0.254: v216.57,234.62 214.98,234.62 A12.R2 | v216.89,185.73 216.57,185.41 211.17,185.41 208.63,182.87 204.82,182.87 v204.19,183.5 | v244.51,126.03 244.19,125.72 232.13,125.72 231.81,126.03 228,126.03 227.68,125.72 215.94,125.72 214.98,126.67 C12.F2 | v248.96,163.5 248,162.55 248,160.96 248.32,160.96 v248.96,160.33 | v251.5,130.48 249.91,128.89 244.83,128.89 v244.51,129.21 | v216.57,198.43 221.97,198.43 222.92,197.47 225.78,197.47 226.73,198.43 234.67,198.43 238.16,194.93 243.56,194.93 244.83,193.66 244.83,190.17 v242.29,190.17 | v242.61,176.52 243.24,175.88 243.56,175.88 245.46,173.98 246.73,173.98 v248.96,171.76
CK00  (via drill 0.61)
  Top 0.254: v174.03,159.69 174.34,160.01 174.34,177.15 171.8,179.69 171.8,183.18 v172.44,183.82 | v156.56,187.63 155.93,188.27 155.93,194.3 156.25,194.61 156.25,195.89 155.93,196.2 155.93,205.09 v156.25,205.41 | v144.82,207 144.18,207.63 v144.18,210.17 | v129.89,210.81 129.89,224.78 130.53,225.41 v130.53,237.16
  Route2 0.254: v174.03,159.69 v175.93,161.59
  Route15 0.254: v192.76,159.69 v194.66,161.59 | v182.92,162.55 v185.77,159.69 | v172.44,183.82 172.12,183.82 v167.04,188.9
  Bottom 0.254: v194.66,161.59 197.84,161.59 B14.S1 | v192.76,159.69 192.44,160.01 186.09,160.01 v185.77,159.69 | v182.92,162.55 182.28,163.18 178.47,163.18 176.88,161.59 v175.93,161.59 | v167.04,188.9 166.72,188.58 159.42,188.58 158.47,187.63 v156.56,187.63 | v156.25,205.41 155.93,205.09 147.04,205.09 145.13,207 v144.82,207 | v144.18,210.17 143.55,210.81 v129.89,210.81 | v130.53,237.16 130.85,236.84 138.78,236.84 139.74,237.8 140.69,237.8 A18.P2
CK00\  (via drill 0.61)
  Top 0.254: v188.95,154.29 B14.T2 188.95,162.55 187.68,162.55 186.41,163.82 v185.46,163.82 | v140.37,240.97 142.59,238.75 v142.59,228.9 | v126.72,225.41 127.99,224.14 v127.99,213.98 | v146.72,212.71 146.4,212.39 v146.4,195.57 | v163.23,194.93 164.82,193.34 v164.82,186.36 | v169.58,180.01 168.63,179.06 168.63,174.61 171.49,171.76 v171.49,169.85
  Route2 0.254: v164.82,186.36 164.82,184.77 v169.58,180.01
  Route15 0.254: v154.98,196.2 155.61,196.2 v157.2,194.61 | v176.57,167.95 179.42,165.09 180.06,165.09 v181.01,164.14
  Bottom 0.254: v188.95,154.29 193.08,154.29 193.71,154.93 195.93,154.93 196.25,155.24 197.84,155.24 B14.U1 | v140.37,240.97 138.78,240.97 A18.N2 | v142.59,228.9 141.32,227.64 139.1,227.64 138.47,227 128.31,227 v126.72,225.41 | v127.99,213.98 145.45,213.98 v146.72,212.71 | v146.4,195.57 154.34,195.57 v154.98,196.2 | v157.2,194.61 157.52,194.93 v163.23,194.93 | v171.49,169.85 171.8,169.53 174.98,169.53 v176.57,167.95 | v181.01,164.14 181.33,163.82 v185.46,163.82
CK01  (via drill 0.61)
  Top 0.254: C16.N1 169.58,107.3 169.58,102.22 C16.R1 | v196.57,154.29 197.2,154.93 197.2,164.14 198.16,165.09 198.16,167.63 B14.P1 | v157.52,109.52 155.29,111.75 155.29,135.88 155.61,136.2 v155.61,137.46 | v158.47,137.78 158.47,164.77 v158.79,165.09
  Bottom 0.254: C16.R1 170.53,101.91 172.76,104.13 C16.P1 | v196.57,154.29 194.03,154.29 193.39,153.66 190.54,153.66 189.58,152.71 B14.V2 | v157.52,109.52 157.83,109.21 164.18,109.21 164.82,108.57 168.95,108.57 169.26,108.25 C16.N1 | v155.61,137.46 155.93,137.78 v158.47,137.78 | v158.79,165.09 160.06,166.36 178.79,166.36 179.42,166.99 180.69,166.99 181.01,167.31 184.82,167.31 185.14,166.99 193.39,166.99 194.66,168.26 B14.P1
CK01\  (via drill 0.61)
  Top 0.254: C16.U2 166.09,92.38 163.87,94.6 C16.T2 164.18,95.55 166.41,97.78 C16.S2 | v194.66,143.18 194.66,151.43 194.98,151.75 B14.V1 | v138.78,137.46 137.83,136.51 v137.83,135.88 | v127.04,135.56 126.72,135.24 v126.72,100.32
  Route2 0.254: v194.66,143.18 193.71,142.23 193.71,140.96 189.9,137.15 187.68,137.15 v186.73,138.1
  Bottom 0.254: v186.73,138.1 186.41,137.78 184.19,137.78 183.23,136.83 181.01,136.83 179.42,138.42 159.1,138.42 158.79,138.74 158.15,138.74 157.83,138.42 139.74,138.42 v138.78,137.46 | v137.83,135.88 137.2,135.24 127.35,135.24 v127.04,135.56 | v126.72,100.32 127.35,99.68 161.33,99.68 161.64,100 164.5,100 165.77,98.73 166.09,98.73 C16.S2
CLR_DF\  (via drill 0.61)
  Top 0.254: v235.62,55.55 235.3,55.87 235.3,60.95 235.94,61.58 v235.94,62.22 | v216.89,108.25 216.25,108.89 216.25,112.07 217.21,113.02 v217.21,115.24 | v220.06,123.18 219.43,123.81 219.43,135.56 220.38,136.51 v220.38,137.46 | v236.89,184.77 235.3,186.36 235.3,195.89 236.89,197.47 v238.16,197.47 | v240.38,212.71 v240.38,217.16 | v236.89,217.16 236.89,224.78 A11.U1
  Route2 0.254: v235.62,55.55 228.32,48.25 228.32,43.8 227.05,42.53 D11.N2 | v217.21,115.24 218.79,116.83 218.79,121.91 v220.06,123.18 | v220.38,137.46 230.54,147.62 230.54,149.21 232.13,150.8 232.13,153.02 v242.61,163.5 | v238.16,197.47 238.16,199.38 241.02,202.24 241.02,212.08 v240.38,212.71
  Route15 0.254: v235.94,62.22 240.07,66.35 235.62,70.79 235.62,72.06 235.3,72.38 235.3,73.97 v231.18,78.09 | v235.94,79.36 238.48,81.9 232.13,88.25 232.13,92.06 217.84,106.35 217.52,106.35 216.89,106.99 v216.89,108.25 | v244.19,165.09 238.48,170.8 238.48,175.88 235.3,179.06 235.3,183.18 v236.89,184.77
  Bottom 0.254: v231.18,78.09 232.45,79.36 v235.94,79.36 | v242.61,163.5 v244.19,165.09 | v240.38,217.16 v236.89,217.16
CLR_DTF\  (via drill 0.61)
  Top 0.254: v211.49,80.32 211.49,91.43 C13.U1 | v208.32,77.14 207.36,76.19 207.36,71.11 206.41,70.16 206.41,52.06 206.09,51.74 206.09,24.75 v206.73,24.12
  Bottom 0.254: v208.32,77.14 v211.49,80.32 | v206.73,24.12 207.05,23.8 212.44,23.8 213.4,22.85 216.25,22.85 217.21,23.8 224.83,23.8 226.41,22.21 D11.U2
COMP+SH  (via drill 0.61)
  Top 0.254: C15.K1 186.41,117.78 186.41,122.22 187.68,123.49 187.68,131.75 188.63,132.7 C14.D2 189.27,133.97 189.27,137.78 v189.58,138.1 | v211.49,267 209.27,269.23 209.27,273.67 208.63,274.31 202.92,274.31 202.92,266.05 v200.7,263.83 | v173.39,260.34 171.49,262.24 v171.49,264.47 | v132.12,268.28 131.16,269.23 131.16,271.77 130.53,272.4 130.53,279.7 v114.97,295.26 | v41.31,294.94 34.64,288.28 v34.64,144.77
  Route15 0.254: v160.06,120.96 v157.52,123.49 | v173.39,126.03 175.3,126.03 178.79,122.54 179.42,122.54 181.01,120.96 181.01,120.32 v183.55,117.78
  Bottom 0.254: C14.H1 197.84,123.49 194.98,123.49 190.85,119.37 188,119.37 186.41,117.78 C15.K1 185.14,117.78 v183.55,117.78 | v189.58,138.1 193.39,138.1 194.66,139.37 C14.B1 | v211.49,267 213.71,267 A12.D2 | v200.7,263.83 199.11,262.24 178.47,262.24 178.15,262.56 176.25,262.56 174.03,260.34 v173.39,260.34 | v171.49,264.47 170.53,265.42 149.26,265.42 147.36,267.32 145.77,267.32 145.13,267.96 136.56,267.96 135.93,267.32 133.07,267.32 v132.12,268.28 | v114.97,295.26 113.38,296.85 67.35,296.85 65.76,295.26 65.12,295.26 64.17,296.22 42.58,296.22 v41.31,294.94 | v34.64,144.77 60.68,118.73 119.1,118.73 121.64,116.19 131.16,116.19 131.8,116.83 133.7,116.83 134.34,116.19 155.29,116.19 v160.06,120.96 | v157.52,123.49 159.74,125.72 173.07,125.72 v173.39,126.03
CSTA  (via drill 0.61)
  Top 0.254: v164.18,34.6 166.09,34.6 D16.P2 | v151.48,21.89 152.12,21.26 152.12,18.72 156.88,13.96 192.44,13.96 192.44,14.27 v196.89,18.72 | v199.43,18.72 201.65,20.94 206.73,20.94 v206.73,21.89 | v252.13,36.5 253.72,34.91 253.72,20.62 255.94,18.4 255.94,15.23 256.58,14.59 v257.85,14.59 | v341.03,15.54 355.32,15.54 v355.32,46.66 | v353.73,48.25 352.78,49.2 352.78,63.17 v352.46,63.49 | v345.48,69.52 345.79,69.84 345.79,71.11 347.06,72.38 347.06,79.68 v346.11,80.63
  Route2 0.254: v151.48,21.89 v164.18,34.6 | v206.73,21.89 208.63,23.8 216.25,23.8 216.57,24.12 217.52,24.12 220.38,26.98 230.86,26.98 v239.75,35.86 | v323.25,91.43 324.2,92.38 324.2,92.7 329.92,98.41 329.92,102.86 325.79,106.99 330.24,111.43 330.24,112.7 v332.14,114.61
  Route15 0.254: v352.46,63.49 351.51,63.49 v345.48,69.52 | v333.41,81.58 333.09,81.58 v323.25,91.43 | v332.14,114.61 332.14,115.24 330.55,116.83 330.55,129.53 327.38,132.7 327.38,134.29 325.79,135.88 C04.C1
  Bottom 0.254: v199.43,18.72 v196.89,18.72 | v239.75,35.86 240.07,36.18 247.05,36.18 247.69,36.82 251.81,36.82 v252.13,36.5 | v257.85,14.59 258.48,13.96 270.86,13.96 271.18,14.27 290.87,14.27 292.14,15.54 v341.03,15.54 | v355.32,46.66 v353.73,48.25 | v346.11,80.63 345.79,80.32 334.68,80.32 v333.41,81.58
CSTA\  (via drill 0.61)
  Route2 0.254: v236.89,229.54 236.89,230.18 241.02,234.3 241.02,237.48 241.65,238.11 241.65,240.02 242.29,240.65 242.29,243.19 241.02,244.46 241.65,245.1 241.65,246.05 242.29,246.68 242.29,247.32 241.02,248.59 240.38,247.96 A10.L2
  Route15 0.254: v236.89,229.54 239.11,227.32 239.11,224.78 245.78,218.11 247.05,218.11 248.32,216.84 248.32,215.89 249.27,214.93 250.23,215.89 250.23,217.48 252.13,219.38 252.77,219.38 253.08,219.06 256.58,219.06 256.89,218.74 257.85,218.74 276.58,200.01 276.58,196.2 292.14,180.64 292.14,171.76 301.98,161.91 301.98,158.1 310.55,149.53 310.55,148.89 311.82,147.62 311.82,146.36 317.54,140.64 317.54,136.2 320.08,133.65 321.66,133.65 C04.D1
DATA  (via drill 0.61)
  Top 0.254: v45.76,241.61 45.76,243.83 A26.M1 | v24.17,239.38 22.58,237.8 22.58,221.6 22.9,221.29 22.9,204.14 22.58,203.82 22.58,151.75 23.53,150.8 v23.53,142.86 | v77.51,107.62 79.09,106.03 | 79.09,106.03 v79.09,52.69 | v182.92,143.5 182.28,144.13 182.28,148.89 181.65,149.53 176.88,149.53 v176.88,149.21 | v79.41,149.53 79.09,149.21 79.09,106.03
  Route15 0.254: v205.14,127.3 205.14,127.62 201.65,131.11 201.01,131.11 v198.79,133.34 | v182.92,143.5 v191.81,134.61 | v176.88,149.21 174.98,149.21 v174.34,149.85 | v157.52,155.24 v160.37,152.39 | v116.24,152.07 v118.78,154.61
  Bottom 0.254: v45.76,241.61 43.53,239.38 v24.17,239.38 | v23.53,142.86 57.19,109.21 75.92,109.21 v77.51,107.62 | v79.09,52.69 79.09,48.88 139.74,48.88 140.69,47.93 CD18.BK2 | v205.14,127.3 207.36,127.3 C13.F1 | v198.79,133.34 198.16,133.97 196.57,133.97 195.93,134.61 v191.81,134.61 | v174.34,149.85 174.03,150.17 162.6,150.17 v160.37,152.39 | v157.52,155.24 156.56,154.29 119.1,154.29 v118.78,154.61 | v116.24,152.07 114.97,150.8 97.83,150.8 96.56,149.53 v79.41,149.53
DATA\  (via drill 0.61)
  Top 0.254: v210.86,128.26 210.86,124.45 C13.H1 | v219.11,189.54 219.75,188.9 219.75,185.09 219.43,184.77 219.43,177.15 220.7,175.88 B12.N1 | v161.64,185.41 161.64,138.1 163.23,136.51 163.23,133.97 C16.D2
  Bottom 0.254: v210.86,128.26 173.07,128.26 169.9,131.43 165.77,131.43 164.18,133.02 C16.D2 | C11.L2 226.73,114.92 226.73,117.78 225.46,117.78 224.51,118.73 214.35,118.73 212.13,120.96 212.13,123.18 211.49,123.18 C13.H1 | v219.11,189.54 218.79,189.22 204.51,189.22 201.33,186.04 182.28,186.04 181.65,185.41 v161.64,185.41
DB_00\  (via drill 0.61)
  Top 0.254: v281.98,68.57 281.34,69.2 v281.34,71.11 | v283.88,72.38 284.83,73.33 284.83,80.32 v284.52,80.63 | v292.14,82.22 292.77,82.86 v292.77,86.66 | v353.41,173.66 353.1,173.98 353.1,176.83 352.46,177.47 352.46,178.11 352.78,178.42 352.78,188.58 v353.1,188.9 | v298.17,262.24 298.17,267.32 297.85,267.64 297.85,271.77 297.22,272.4 A06.B1 | v310.55,256.53 311.19,255.89 311.19,253.04 310.55,252.4 310.55,248.59 311.19,247.96 311.19,245.73 310.55,245.1 310.55,242.24 311.19,241.61 311.19,239.38 310.55,238.75 310.55,235.89 311.19,235.26 311.19,233.99 v310.87,233.67
  Route2 0.254: v287.69,89.21 287.69,90.47 288.64,91.43 288.64,96.51 309.92,117.78 309.92,119.05 310.87,120 310.87,124.45 323.25,136.83 323.25,138.74 323.57,139.05 323.57,143.81 v350.56,170.8 | v350.87,190.17 347.7,193.34 348.02,193.66 348.02,196.2 B02.D1
  Route15 0.254: v315.31,232.71 315.31,232.4 316.58,231.13 316.58,230.49 v328.97,218.11 | v334.05,214.62 334.05,212.39 346.11,200.33 346.11,198.74 347.38,197.47 B02.D1
  Bottom 0.254: v281.98,68.57 284.83,68.57 286.74,70.47 288.96,70.47 289.6,71.11 293.72,71.11 294.99,72.38 298.17,72.38 298.17,70.79 297.53,70.16 D06.B1 | v281.34,71.11 282.61,72.38 v283.88,72.38 | v284.52,80.63 286.1,82.22 v292.14,82.22 | v292.77,86.66 291.82,87.62 289.28,87.62 v287.69,89.21 | v350.56,170.8 v353.41,173.66 | v353.1,188.9 351.83,190.17 v350.87,190.17 | v298.17,262.24 298.49,261.93 305.15,261.93 v310.55,256.53 | v310.87,233.67 311.19,233.35 314.68,233.35 v315.31,232.71 | v328.97,218.11 332.14,214.93 333.73,214.93 v334.05,214.62
DB_01\  (via drill 0.61)
  Top 0.254: v303.25,67.93 301.98,69.2 301.98,72.06 302.3,72.38 302.3,78.73 301.66,79.36 v301.66,87.3 | v310.23,105.4 310.55,105.72 310.55,106.67 311.19,107.3 313.09,107.3 v313.09,108.89 | v331.82,139.05 330.55,140.32 v330.55,141.59 | v354.05,167.95 354.68,168.58 354.68,170.17 355.32,170.8 355.32,174.61 v354.37,175.56 | v299.76,267.32 301.98,269.55 v301.98,283.83 | v361.99,275.9 361.99,239.38 361.67,239.06 361.67,234.3 360.72,233.35 v360.72,232.08 | v369.92,218.43 369.61,218.11 369.61,212.08 v369.92,211.76
  Route2 0.254: v303.25,67.93 299.12,63.81 297.53,63.81 D06.D1 | v313.09,108.89 310.55,111.43 326.11,126.99 326.11,128.89 326.74,129.53 326.74,133.97 v331.82,139.05 | v329.28,144.77 332.14,147.62 334.36,147.62 343.89,157.15 344.21,157.15 v345.16,158.1 | v348.33,162.23 v354.05,167.95 | v369.61,222.87 369.61,221.29 370.88,220.02 370.56,219.7 370.56,219.06 v369.92,218.43 | v369.92,211.76 369.92,211.12 364.84,206.05 364.84,205.73 v353.1,193.98
  Route15 0.254: v321.98,92.7 321.35,92.7 310.23,103.81 v310.23,105.4 | v330.55,141.59 330.55,142.23 330.24,142.55 330.24,143.81 v329.28,144.77
  Bottom 0.254: v301.66,87.3 301.98,87.62 304.52,87.62 307.06,90.16 307.06,90.79 307.69,91.43 311.5,91.43 312.14,90.79 319.76,90.79 321.66,92.7 v321.98,92.7 | v345.16,158.1 348.33,161.28 v348.33,162.23 | v354.37,175.56 352.46,177.47 352.46,187.95 353.41,187.95 355.32,189.85 355.32,193.34 353.1,193.34 | 353.1,193.34 351.51,193.34 B02.E1 | v299.76,267.32 297.85,267.32 297.53,267 A06.D1 | v301.98,283.83 302.3,284.15 353.73,284.15 v361.99,275.9 | v360.72,232.08 361.99,232.08 362.94,233.03 368.65,233.03 371.19,230.49 371.19,223.19 369.92,223.19 v369.61,222.87 | 353.1,193.34 v353.1,193.98
DB_02\  (via drill 0.61)
  Top 0.254: 301.66,250.49 301.66,258.11 300.07,259.7 A06.E1 | 301.66,250.49 301.66,225.09 300.71,224.14 300.71,212.08 301.66,211.12 301.66,183.82 301.34,183.5 301.34,157.79 301.66,157.47 301.66,139.05 301.34,138.74 301.34,91.43 300.71,90.79 300.71,79.36 301.66,78.41 301.66,72.69 301.34,72.38 301.34,68.88 301.66,68.57 301.66,66.35 300.39,65.08 300.39,60.95 D06.E1 | v349.92,202.87 349.6,202.55 349.6,182.55 350.56,181.6 B02.K1 | v342.94,210.81 342.62,211.12 342.62,214.3 v342.94,214.62 | v332.78,213.98 332.46,214.3 v332.46,222.87 | v348.97,233.67 349.29,233.99 349.29,242.87 348.97,243.19 v348.97,248.91 | 301.66,250.49 v301.98,250.49
  Route2 0.254: v332.46,222.87 332.46,223.19 v338.17,228.9 | v348.97,233.67 v344.84,229.54
  Route15 0.254: v349.92,202.87 349.92,203.19 349.29,203.82 349.29,204.46 v342.94,210.81
  Bottom 0.254: v342.94,214.62 341.98,213.67 333.09,213.67 v332.78,213.98 | v338.17,228.9 339.13,229.86 344.52,229.86 v344.84,229.54 | v348.97,248.91 348.33,249.54 341.35,249.54 338.49,252.4 336.27,252.4 335.95,252.08 326.11,252.08 325.79,252.4 317.22,252.4 314.04,249.23 306.11,249.23 304.84,250.49 v301.98,250.49
DB_03\  (via drill 0.61)
  Top 0.254: v301.34,64.12 301.34,55.55 300.39,54.6 D06.H1 | v308.96,72.38 308.65,72.69 308.65,75.24 v309.28,75.87 | v353.1,137.78 352.78,138.1 352.78,140.64 353.73,141.59 v353.73,146.67 | v350.87,146.67 349.92,147.62 349.92,154.61 349.29,155.24 349.29,155.88 350.56,157.15 350.56,158.74 352.14,160.33 352.14,162.55 351.19,163.5 351.19,166.04 349.6,167.63 349.6,168.9 350.56,169.85 351.51,169.85 351.51,171.12 v350.56,172.07 | v300.39,254.94 300.39,256.53 A06.H1 | v306.11,252.4 305.15,251.45 305.15,250.18 305.47,249.86 v305.47,248.59 | v348.65,213.35 v348.65,218.11 | v345.48,197.15 343.25,194.93 343.25,186.04 344.84,184.46 v344.84,182.55
  Route2 0.254: v301.34,64.12 301.34,64.44 308.96,72.06 v308.96,72.38 | v323.25,92.7 323.25,93.02 v328.97,98.73 | v344.21,101.91 341.35,104.76 v353.41,116.83 | v345.48,197.15 v351.19,202.87
  Route15 0.254: v318.49,88.57 v314.36,84.44 | v356.27,120.96 356.27,121.27 354.37,123.18 354.37,124.77 352.78,126.35 352.78,127.94 357.86,133.02 v353.1,137.78 | v336.27,237.8 336.27,235.57 342.62,229.22 342.62,226.36 342.94,226.05 342.94,223.83 v348.65,218.11 | v348.65,213.35 348.65,211.76 347.7,210.81 347.7,207 349.92,204.77 349.92,204.14 v351.19,202.87 | v344.84,182.55 345.79,182.55 v347.06,181.28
